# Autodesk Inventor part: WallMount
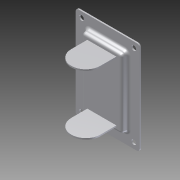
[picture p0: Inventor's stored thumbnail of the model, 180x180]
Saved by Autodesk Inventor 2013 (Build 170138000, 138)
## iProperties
Created: 2004-11
Document SubType Name: Modeling
Designer: Autodesk, Inc.
Manufacturer: Standard
Standards Organization: Custom
Description: SWING ARM WALL MOUNT
Mass: 35.0537 g
Surface Area: 194.518 cm^2
Volume: 35.0537 cm^3
Density: 1 g/cm^3
Material: Allgemein
CAGE: 1LJX3
Dept. ID: Product Design
Description #2: ---
Finish #1: ---
Finish #2: ---
Material ID: ---
Project Number: ---
Author: Autodesk, Inc.
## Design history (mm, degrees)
sketch "Sketch2"
  geometry: L1 (-31.75, 50.8)-(31.75, 50.8); L2 (34.925, 47.625)-(34.925, -47.625); L3 (31.75, -50.8)-(-31.75, -50.8); L4 (-34.925, -47.625)-(-34.925, 47.625); A1 r 3.175 centre (-31.75, 47.625) between (-31.75, 50.8) and (-34.925, 47.625); A2 r 3.175 centre (31.75, 47.625) between (34.925, 47.625) and (31.75, 50.8); A3 r 3.175 centre (31.75, -47.625) between (31.75, -50.8) and (34.925, -47.625); A4 r 3.175 centre (-31.75, -47.625) between (-34.925, -47.625) and (-31.75, -50.8); 7 further points
  constraints: 8 end point, 8 point on circle, 8 point on line, 8 tangent, 4 centre point, 3 equal radius, 2 midpoint, 2 parallel, 1 horizontal, 1 horizontal alignment, 1 perpendicular, 1 vertical alignment
  dimensions: "d0" = 69.85 distance of point (34.925, -50.8) point (-34.925, -50.8); "d1" = 101.6 distance of point (-34.925, -50.8) point (-34.925, 50.8); "d4" = 3.175 radius of A1
extrude "Extrusion1" new body sketch "Sketch2" distance "d2" = 1.524; taper "d3" = 0 deg
sketch "Sketch3"
  geometry: L1 (-19.05, 38.1)-(19.05, 38.1); L2 (22.225, 34.925)-(22.225, -34.925); L3 (19.05, -38.1)-(-19.05, -38.1); L4 (-22.225, -34.925)-(-22.225, 34.925); L5 (31.75, -50.8)-(-31.75, -50.8) reference; L6 (-34.925, -47.625)-(-34.925, 47.625) reference; A1 r 3.175 centre (-19.05, 34.925) between (-19.05, 38.1) and (-22.225, 34.925); A2 r 3.175 centre (19.05, 34.925) between (22.225, 34.925) and (19.05, 38.1); A3 r 3.175 centre (19.05, -34.925) between (19.05, -38.1) and (22.225, -34.925); A4 r 3.175 centre (-19.05, -34.925) between (-22.225, -34.925) and (-19.05, -38.1); 3 further points
  constraints: 8 end point, 8 point on circle, 8 tangent, 4 centre point, 3 equal radius, 2 midpoint, 2 parallel, 1 horizontal, 1 horizontal alignment, 1 perpendicular, 1 vertical alignment
  dimensions: "d7" = 3.175 radius of A1; "d8" = 12.7 distance between parallel lines of L5 L3; "d9" = 12.7 distance between parallel lines of L6 L4
extrude "Extrusion2" join sketch "Sketch3" distance "d10" = 6.35; taper "d11" = 0 deg
fillet "Fillet1" dims "d12" = 3.175
workplane "Work Plane1"
sketch "Sketch4" dims "d15" = 31.75
  geometry: L1 (-15.875, 0)-(15.875, 0); L2 (15.875, 0)-(15.875, 25.4); L3 (15.875, 25.4)-(-15.875, 25.4); L4 (-15.875, 25.4)-(-15.875, 0); L5 (-31.75, 0)-(31.75, 0) reference; 4 further points
  constraints: 8 end point, 3 midpoint, 2 parallel, 1 coincident, 1 collinear, 1 horizontal, 1 horizontal alignment, 1 perpendicular, 2 other
  dimensions: "d14" = 25.4 distance between parallel lines of L3 L1
extrude "Extrusion3" join sketch "Sketch4" distance "d16" = 1.524; taper "d17" = 0 deg
mirror "Mirror1"
sketch "Sketch5"
  geometry: L1 (-34.925, -47.625)-(-34.925, 47.625) reference; L2 (31.75, -50.8)-(-31.75, -50.8) reference; C1 r 2.54 at (-28.575, -44.45); 1 further point
  constraints: 1 centre point
  dimensions: "d18" = 5.08 diameter of C1; "d19" = 6.35 distance from line of L1 C1.centre; "d20" = 6.35 distance from line of L2 C1.centre
extrude "Extrusion4" cut sketch "Sketch5" stored distance "d21" = 1.524; taper "d22" = 0 deg
mirror "Mirror2"
mirror "Mirror3"
body "Solid1"
other parameters: "d13" = -31.75
